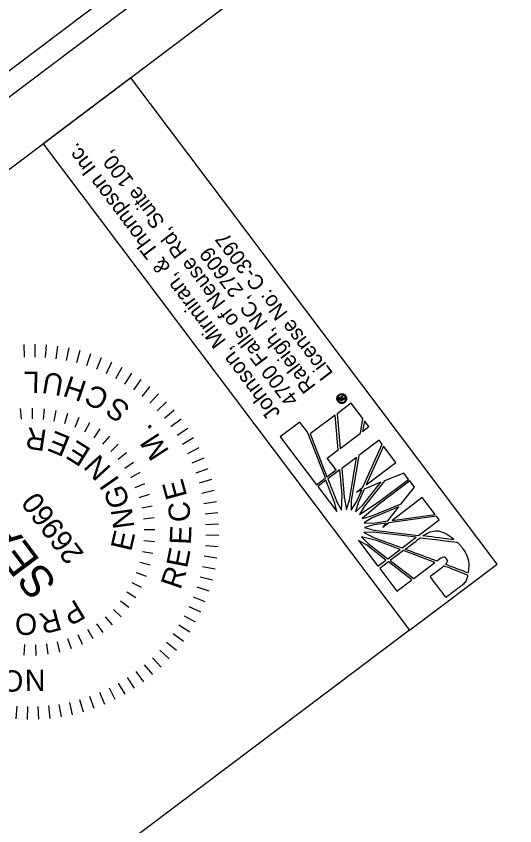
# Model space of a CAD drawing. Extents: x 1262917 to 1264804, y 775326 to 777329.
# Drawn here: x 1263048.7 to 1263156.4, y 776605.9 to 776780.7 of the extents above; entities that cross this region are included whole.
import ezdxf

# ---------------------------------------------------------------- set-up
doc = ezdxf.new("R2010")
doc.units = 0
for name, color, linetype in [('Default', 7, 'Continuous'), ('Sheet Data Field CELL', 7, 'Continuous'), ('Sheet Plan CELL', 7, 'Continuous'), ('Sheet Plot Border Inside CELL', 7, 'Continuous'), ('Sheet Plot Border Outside CELL', 7, 'Continuous'), ('Sheet Typical CELL', 7, 'Continuous')]:
    doc.layers.add(name, color=color, linetype=linetype)

msp = doc.modelspace()

# ---------------------------------------------------------------- linework, layer by layer
at = {"layer": 'Default'}
for p, q in [((1263050.34, 776709.83), (1263050.45, 776707.08)), ((1263052.78, 776709.86), (1263052.73, 776707.1)), ((1263055.23, 776709.74), (1263055, 776706.99)), ((1263057.65, 776709.47), (1263057.27, 776706.73)), ((1263060.06, 776709.05), (1263059.51, 776706.35)), ((1263062.45, 776708.49), (1263061.73, 776705.83)), ((1263064.79, 776707.79), (1263063.92, 776705.17)), ((1263067.08, 776706.94), (1263066.06, 776704.38)), ((1263069.33, 776705.96), (1263068.14, 776703.47)), ((1263071.5, 776704.84), (1263070.17, 776702.43)), ((1263073.61, 776703.6), (1263072.13, 776701.27)), ((1263075.63, 776702.24), (1263074.02, 776700)), ((1263077.58, 776700.75), (1263075.83, 776698.61)), ((1263079.42, 776699.14), (1263077.55, 776697.12)), ((1263081.17, 776697.43), (1263079.18, 776695.52)), ((1263049.6, 776695.96), (1263049.81, 776693.67)), ((1263052.19, 776696.07), (1263052.17, 776693.76)), ((1263054.76, 776695.92), (1263054.52, 776693.63)), ((1263057.3, 776695.53), (1263056.85, 776693.27)), ((1263082.81, 776695.62), (1263080.71, 776693.83)), ((1263059.8, 776694.89), (1263059.13, 776692.69)), ((1263062.23, 776694.02), (1263061.35, 776691.89)), ((1263084.34, 776693.71), (1263082.13, 776692.05)), ((1263064.56, 776692.91), (1263063.47, 776690.88)), ((1263066.78, 776691.58), (1263065.5, 776689.67)), ((1263085.75, 776691.71), (1263083.45, 776690.19)), ((1263068.85, 776690.05), (1263067.39, 776688.27)), ((1263070.76, 776688.33), (1263069.14, 776686.7)), ((1263087.03, 776689.63), (1263084.65, 776688.25)), ((1263072.51, 776686.43), (1263070.73, 776684.96)), ((1263088.19, 776687.48), (1263085.73, 776686.24)), ((1263089.22, 776685.26), (1263086.68, 776684.17)), ((1263074.06, 776684.37), (1263072.15, 776683.07)), ((1263090.11, 776682.98), (1263087.51, 776682.05)), ((1263075.4, 776682.16), (1263073.38, 776681.06)), ((1263074.41, 776678.93), (1263076.53, 776679.83)), ((1263090.86, 776680.65), (1263088.21, 776679.88)), ((1263091.47, 776678.28), (1263088.78, 776677.67)), ((1263077.42, 776677.43), (1263075.22, 776676.73)), ((1263091.94, 776675.88), (1263089.21, 776675.44)), ((1263078.07, 776674.93), (1263075.82, 776674.45)), ((1263078.49, 776672.39), (1263076.2, 776672.13)), ((1263092.26, 776673.46), (1263089.51, 776673.18)), ((1263092.43, 776671.02), (1263089.67, 776670.91)), ((1263078.65, 776669.81), (1263076.36, 776669.78)), ((1263078.57, 776667.23), (1263076.28, 776667.42)), ((1263092.45, 776668.57), (1263089.7, 776668.63)), ((1263092.33, 776666.13), (1263089.58, 776666.35)), ((1263078.24, 776664.68), (1263075.98, 776665.09)), ((1263092.06, 776663.7), (1263089.33, 776664.09)), ((1263077.67, 776662.17), (1263075.45, 776662.79)), ((1263091.65, 776661.29), (1263088.94, 776661.84)), ((1263076.85, 776659.72), (1263074.71, 776660.55)), ((1263075.8, 776657.37), (1263073.75, 776658.4)), ((1263091.08, 776658.91), (1263088.42, 776659.62)), ((1263090.38, 776656.57), (1263087.77, 776657.44)), ((1263074.53, 776655.12), (1263072.59, 776656.35)), ((1263089.54, 776654.27), (1263086.98, 776655.3)), ((1263073.05, 776653.01), (1263071.24, 776654.42)), ((1263088.56, 776652.03), (1263086.06, 776653.21)), ((1263071.37, 776651.06), (1263069.7, 776652.63)), ((1263069.51, 776649.27), (1263068, 776651)), ((1263087.44, 776649.85), (1263085.03, 776651.18)), ((1263065.32, 776646.27), (1263064.17, 776648.26)), ((1263067.49, 776647.67), (1263066.16, 776649.54)), ((1263086.2, 776647.74), (1263083.86, 776649.22)), ((1263060.63, 776644.14), (1263059.88, 776646.31)), ((1263063.03, 776645.09), (1263062.08, 776647.18)), ((1263084.83, 776645.72), (1263082.59, 776647.34)), ((1263050.48, 776642.74), (1263050.6, 776645.03)), ((1263053.05, 776642.71), (1263052.96, 776645.01)), ((1263055.62, 776642.94), (1263055.31, 776645.22)), ((1263058.16, 776643.42), (1263057.62, 776645.66)), ((1263083.34, 776643.78), (1263081.21, 776645.52)), ((1263081.74, 776641.93), (1263079.71, 776643.8)), ((1263080.03, 776640.19), (1263078.12, 776642.17)), ((1263076.3, 776637.02), (1263074.65, 776639.22)), ((1263078.21, 776638.55), (1263076.43, 776640.65)), ((1263074.3, 776635.61), (1263072.78, 776637.91)), ((1263070.07, 776633.16), (1263068.84, 776635.63)), ((1263072.22, 776634.32), (1263070.84, 776636.71)), ((1263065.57, 776631.24), (1263064.64, 776633.84)), ((1263067.85, 776632.13), (1263066.77, 776634.67)), ((1263058.48, 776629.42), (1263058.03, 776632.14)), ((1263060.88, 776629.89), (1263060.27, 776632.57)), ((1263063.25, 776630.49), (1263062.48, 776633.14)), ((1263048.72, 776629.02), (1263048.95, 776631.77)), ((1263051.17, 776628.9), (1263051.22, 776631.66)), ((1263053.61, 776628.92), (1263053.5, 776631.68)), ((1263056.05, 776629.1), (1263055.78, 776631.84))]:
    msp.add_line(p, q, dxfattribs=at)
at = {"layer": 'Sheet Data Field CELL'}
for p, q in [((1263119.67, 776698.63), (1263119.84, 776698.76)), ((1263119.84, 776698.76), (1263119.67, 776698.63)), ((1263119.67, 776698.63), (1263119.67, 776698.64)), ((1263119.83, 776698.76), (1263119.84, 776698.76)), ((1263121.05, 776697.16), (1263118.01, 776694.86)), ((1263118.19, 776697.51), (1263118.34, 776697.63)), ((1263118.34, 776697.63), (1263118.19, 776697.51)), ((1263118.63, 776697.84), (1263118.59, 776697.89)), ((1263118.63, 776697.84), (1263118.77, 776697.95)), ((1263118.77, 776697.95), (1263118.63, 776697.84)), ((1263118.86, 776697.54), (1263118.63, 776697.84)), ((1263118.76, 776697.97), (1263118.77, 776697.95)), ((1263118.77, 776697.95), (1263118.88, 776697.82)), ((1263119.61, 776698.1), (1263118.86, 776697.54)), ((1263118.88, 776697.82), (1263119.05, 776697.95)), ((1263118.95, 776698.09), (1263119.09, 776698.19)), ((1263119.09, 776698.19), (1263118.95, 776698.09)), ((1263119.05, 776697.95), (1263118.95, 776698.09)), ((1263118.95, 776698.09), (1263118.95, 776698.09)), ((1263119.08, 776698.2), (1263119.09, 776698.19)), ((1263119.09, 776698.19), (1263119.19, 776698.05)), ((1263119.19, 776698.05), (1263119.48, 776698.27)), ((1263119.48, 776698.27), (1263119.61, 776698.1)), ((1263123.56, 776693.83), (1263121.05, 776697.16)), ((1263117.62, 776694.58), (1263112.21, 776690.49)), ((1263118.24, 776687.06), (1263117.62, 776694.58)), ((1263118.01, 776694.86), (1263118.64, 776687.36)), ((1263123.03, 776690.68), (1263123.56, 776693.83)), ((1263123.93, 776693.35), (1263123.51, 776691.04)), ((1263124.89, 776692.08), (1263123.93, 776693.35)), ((1263109.97, 776693.06), (1263105.75, 776689.87)), ((1263111.63, 776690.86), (1263109.97, 776693.06)), ((1263123.51, 776691.04), (1263124.89, 776692.08)), ((1263105.75, 776689.87), (1263113.53, 776679.55)), ((1263115.48, 776681.02), (1263111.63, 776690.86)), ((1263112.21, 776690.49), (1263115.78, 776681.24)), ((1263118.64, 776687.36), (1263123.03, 776690.68)), ((1263127.1, 776689.14), (1263122.7, 776685.82)), ((1263123.6, 776678.99), (1263127.76, 776688.28)), ((1263127.76, 776688.28), (1263127.1, 776689.14)), ((1263115.88, 776685.28), (1263118.24, 776687.06)), ((1263128.04, 776687.85), (1263124.31, 776679.52)), ((1263130.69, 776684.34), (1263128.04, 776687.85)), ((1263117.78, 776682.76), (1263115.88, 776685.28)), ((1263122.19, 776685.43), (1263119.04, 776683.06)), ((1263120.67, 776676.18), (1263122.19, 776685.43)), ((1263122.7, 776685.82), (1263121.07, 776676.14)), ((1263115.81, 776681.27), (1263117.78, 776682.76)), ((1263119.04, 776683.06), (1263119.55, 776676.82)), ((1263124.31, 776679.52), (1263130.69, 776684.34)), ((1263115.43, 776680.98), (1263115.48, 776681.02)), ((1263115.78, 776681.24), (1263115.81, 776681.27)), ((1263118.61, 776682.73), (1263115.98, 776680.8)), ((1263119.08, 776677.39), (1263118.61, 776682.73)), ((1263132.41, 776682.06), (1263128.23, 776680.4)), ((1263133.43, 776680.7), (1263132.41, 776682.06)), ((1263113.53, 776679.55), (1263115.43, 776680.98)), ((1263115.61, 776680.52), (1263113.84, 776679.19)), ((1263117.54, 776675.59), (1263115.61, 776680.52)), ((1263115.98, 776680.8), (1263118, 776675.73)), ((1263123.47, 776675.06), (1263127.46, 776680.07)), ((1263127.46, 776680.07), (1263123.89, 776678.61)), ((1263128.23, 776680.4), (1263123.91, 776674.93)), ((1263126.89, 776675.76), (1263133.43, 776680.7)), ((1263133.7, 776680.36), (1263127.15, 776675.42)), ((1263134.71, 776679.01), (1263133.7, 776680.36)), ((1263113.84, 776679.19), (1263117.93, 776673.73)), ((1263122.17, 776677.91), (1263123.6, 776678.99)), ((1263122.17, 776675.87), (1263123.33, 776678.39)), ((1263123.33, 776678.39), (1263122.17, 776677.91)), ((1263123.89, 776678.61), (1263122.55, 776675.6)), ((1263131.87, 776675.42), (1263134.71, 776679.01)), ((1263118.94, 776674.07), (1263119.08, 776677.39)), ((1263119.55, 776676.82), (1263120.03, 776674.21)), ((1263120.03, 776674.21), (1263120.67, 776676.18)), ((1263121.07, 776676.14), (1263121.05, 776674.08)), ((1263121.05, 776674.08), (1263122.17, 776675.87)), ((1263122.83, 776673.09), (1263126.89, 776675.76)), ((1263136.41, 776676.81), (1263129.89, 776671.84)), ((1263139.17, 776673.15), (1263136.41, 776676.81)), ((1263117.93, 776673.73), (1263117.54, 776675.59)), ((1263118, 776675.73), (1263118.94, 776674.07)), ((1263122.55, 776675.6), (1263122.02, 776673.71)), ((1263122.02, 776673.71), (1263123.47, 776675.06)), ((1263123.91, 776674.93), (1263122.83, 776673.09)), ((1263127.15, 776675.42), (1263123.44, 776672.28)), ((1263131.31, 776674.74), (1263125.45, 776672.31)), ((1263125.52, 776672.8), (1263131.87, 776675.42)), ((1263128.96, 776671.73), (1263131.31, 776674.74)), ((1263123.44, 776672.28), (1263125.52, 776672.8)), ((1263125.45, 776672.31), (1263123.83, 776671.31)), ((1263139.46, 776672.77), (1263129.19, 776671.31)), ((1263129.89, 776671.84), (1263139.17, 776673.15)), ((1263140.07, 776671.96), (1263139.46, 776672.77)), ((1263123.83, 776671.31), (1263125.81, 776671.28)), ((1263125.95, 776670.86), (1263123.93, 776670.28)), ((1263125.81, 776671.28), (1263128.96, 776671.73)), ((1263128.6, 776671.24), (1263125.95, 776670.86)), ((1263129.19, 776671.31), (1263127.89, 776670.33)), ((1263127.89, 776670.33), (1263128.6, 776671.24)), ((1263135.62, 776668.6), (1263140.07, 776671.96)), ((1263125.81, 776669.32), (1263123.76, 776669.26)), ((1263123.76, 776669.26), (1263126.12, 776668.11)), ((1263123.93, 776670.28), (1263125.92, 776669.73)), ((1263135.1, 776668.21), (1263125.81, 776669.32)), ((1263125.92, 776669.73), (1263135.62, 776668.6)), ((1263124.33, 776666.54), (1263122.65, 776667.48)), ((1263122.65, 776667.48), (1263126.81, 776661.95)), ((1263126.49, 776667.5), (1263123.31, 776668.28)), ((1263123.31, 776668.28), (1263124.71, 776666.83)), ((1263126.12, 776668.11), (1263132.04, 776665.9)), ((1263131.61, 776665.57), (1263126.49, 776667.5)), ((1263132.04, 776665.9), (1263135.1, 776668.21)), ((1263128.57, 776663.28), (1263124.33, 776666.54)), ((1263124.71, 776666.83), (1263128.95, 776663.57)), ((1263128.95, 776663.57), (1263131.61, 776665.57)), ((1263132.32, 776665.31), (1263129.47, 776663.16)), ((1263139.13, 776662.75), (1263132.32, 776665.31)), ((1263126.81, 776661.95), (1263128.57, 776663.28)), ((1263129.12, 776662.89), (1263127.22, 776661.46)), ((1263134.18, 776659.01), (1263129.12, 776662.89)), ((1263129.47, 776663.16), (1263134.55, 776659.29)), ((1263134.55, 776659.29), (1263139.13, 776662.75)), ((1263127.22, 776661.46), (1263130.93, 776656.55)), ((1263130.93, 776656.55), (1263134.18, 776659.01))]:
    msp.add_line(p, q, dxfattribs=at)
msp.add_lwpolyline([(1263152.54, 776662.43), (1263073.5, 776767.37), (1263054.56, 776753.11), (1263133.61, 776648.16)], close=True, dxfattribs=at)
for points in [[(1263118.96, 776698.6), (1263119, 776698.64), (1263119.02, 776698.66), (1263119.05, 776698.68), (1263119.11, 776698.77), (1263119.23, 776698.61)], [(1263118.64, 776687.36), (1263123.03, 776690.68), (1263123.56, 776693.83), (1263121.05, 776697.16), (1263118.01, 776694.86), (1263118.64, 776687.36), (1263118.64, 776687.36)], [(1263115.78, 776681.24), (1263115.81, 776681.27), (1263117.78, 776682.76), (1263115.88, 776685.28), (1263118.24, 776687.06), (1263117.62, 776694.58), (1263112.21, 776690.49), (1263115.78, 776681.24)], [(1263124.89, 776692.08), (1263124.89, 776692.08), (1263123.93, 776693.35), (1263123.51, 776691.04), (1263124.89, 776692.08)], [(1263105.75, 776689.87), (1263113.53, 776679.55), (1263115.43, 776680.98), (1263115.48, 776681.02), (1263111.63, 776690.86), (1263109.97, 776693.06), (1263105.75, 776689.87)], [(1263121.05, 776674.08), (1263122.17, 776675.87), (1263123.33, 776678.39), (1263122.17, 776677.91), (1263123.6, 776678.99), (1263127.76, 776688.28), (1263127.1, 776689.14), (1263122.7, 776685.82), (1263121.07, 776676.14), (1263121.05, 776674.08)], [(1263130.69, 776684.34), (1263128.04, 776687.85), (1263124.31, 776679.52), (1263130.69, 776684.34)], [(1263120.03, 776674.21), (1263120.67, 776676.18), (1263122.19, 776685.43), (1263119.04, 776683.06), (1263119.55, 776676.82), (1263120.03, 776674.21)], [(1263118.94, 776674.07), (1263119.08, 776677.39), (1263118.61, 776682.73), (1263115.98, 776680.8), (1263118, 776675.73), (1263118.94, 776674.07)], [(1263122.83, 776673.09), (1263126.89, 776675.76), (1263133.43, 776680.7), (1263132.41, 776682.06), (1263128.23, 776680.4), (1263123.91, 776674.93), (1263122.83, 776673.09)], [(1263117.54, 776675.59), (1263115.61, 776680.52), (1263113.84, 776679.19), (1263117.93, 776673.73), (1263117.54, 776675.59)], [(1263122.02, 776673.71), (1263123.47, 776675.06), (1263127.46, 776680.07), (1263123.89, 776678.61), (1263122.55, 776675.6), (1263122.02, 776673.71)], [(1263125.52, 776672.8), (1263131.87, 776675.42), (1263134.71, 776679.01), (1263133.7, 776680.36), (1263127.15, 776675.42), (1263123.44, 776672.28), (1263125.52, 776672.8)], [(1263139.17, 776673.15), (1263136.41, 776676.81), (1263129.89, 776671.84), (1263139.17, 776673.15)], [(1263123.83, 776671.31), (1263125.81, 776671.28), (1263128.96, 776671.73), (1263131.31, 776674.74), (1263125.45, 776672.31), (1263123.83, 776671.31)], [(1263123.93, 776670.28), (1263125.92, 776669.73), (1263135.62, 776668.6), (1263140.07, 776671.96), (1263139.46, 776672.77), (1263129.19, 776671.31), (1263127.89, 776670.33), (1263128.6, 776671.24), (1263125.95, 776670.86), (1263123.93, 776670.28)], [(1263132.04, 776665.9), (1263135.1, 776668.21), (1263125.81, 776669.32), (1263123.76, 776669.26), (1263126.12, 776668.11), (1263132.04, 776665.9)], [(1263124.33, 776666.54), (1263122.65, 776667.48), (1263126.81, 776661.95), (1263128.57, 776663.28), (1263124.33, 776666.54)], [(1263128.95, 776663.57), (1263131.61, 776665.57), (1263126.49, 776667.5), (1263123.31, 776668.28), (1263124.71, 776666.83), (1263128.95, 776663.57)], [(1263139.13, 776662.75), (1263132.32, 776665.31), (1263129.47, 776663.16), (1263134.55, 776659.29), (1263139.13, 776662.75)], [(1263134.18, 776659.01), (1263129.12, 776662.89), (1263127.22, 776661.46), (1263130.93, 776656.55), (1263134.18, 776659.01)]]:
    msp.add_lwpolyline(points, dxfattribs=at)
for points, degree in [([(1263118.19, 776697.51), (1263118.01, 776697.74), (1263117.94, 776698), (1263117.98, 776698.28), (1263118, 776698.56), (1263118.14, 776698.79), (1263118.37, 776698.97)], 3), ([(1263119.67, 776698.64), (1263119.53, 776698.82), (1263119.35, 776698.93), (1263119.12, 776698.97), (1263118.89, 776699), (1263118.68, 776698.94), (1263118.5, 776698.8), (1263118.31, 776698.66), (1263118.2, 776698.47), (1263118.17, 776698.25), (1263118.14, 776698.02), (1263118.2, 776697.82), (1263118.34, 776697.63)], 3), ([(1263119.84, 776698.76), (1263120.01, 776698.53), (1263120.07, 776698.27), (1263120.03, 776697.98), (1263120, 776697.7), (1263119.86, 776697.47), (1263119.63, 776697.3), (1263119.4, 776697.12), (1263119.14, 776697.05), (1263118.87, 776697.1), (1263118.59, 776697.15), (1263118.36, 776697.28), (1263118.19, 776697.51)], 3), ([(1263118.34, 776697.63), (1263118.48, 776697.44), (1263118.66, 776697.33), (1263118.88, 776697.3), (1263119.11, 776697.27), (1263119.33, 776697.32), (1263119.51, 776697.46), (1263119.69, 776697.6), (1263119.81, 776697.79), (1263119.84, 776698.02), (1263119.87, 776698.25), (1263119.81, 776698.45), (1263119.67, 776698.63)], 3), ([(1263118.37, 776698.97), (1263118.6, 776699.14), (1263118.86, 776699.21), (1263119.15, 776699.18), (1263119.43, 776699.13), (1263119.66, 776698.99), (1263119.83, 776698.76)], 3), ([(1263118.83, 776698.38), (1263118.82, 776698.45), (1263118.87, 776698.53), (1263118.96, 776698.6)], 2), ([(1263119.23, 776698.61), (1263119.21, 776698.56), (1263119.17, 776698.51), (1263119.12, 776698.47), (1263119.05, 776698.42), (1263119.02, 776698.38), (1263119.01, 776698.35)], 3), ([(1263118.59, 776697.89), (1263118.45, 776698.08), (1263118.45, 776698.24), (1263118.6, 776698.35), (1263118.67, 776698.4), (1263118.75, 776698.41), (1263118.83, 776698.38)], 3), ([(1263118.95, 776698.09), (1263118.86, 776698.2), (1263118.79, 776698.23), (1263118.73, 776698.19), (1263118.67, 776698.14), (1263118.68, 776698.08), (1263118.76, 776697.97)], 3), ([(1263119.01, 776698.35), (1263119.01, 776698.32), (1263119.03, 776698.26), (1263119.08, 776698.2)], 2), ([(1263136.54, 776668.5), (1263136.54, 776668.5), (1263143.37, 776667.65), (1263143.37, 776667.65), (1263141.5, 776669.17), (1263138.85, 776670.1), (1263136.54, 776668.5)], 3), ([(1263141.65, 776663.54), (1263141.87, 776663.25), (1263141.89, 776662.87), (1263141.43, 776662.36), (1263141.43, 776662.36), (1263146.27, 776660.48), (1263146.27, 776660.48), (1263146.59, 776662.43), (1263145.96, 776664.67), (1263144.86, 776666.14), (1263144.57, 776666.52), (1263144.32, 776666.79), (1263143.93, 776667.13), (1263143.93, 776667.13), (1263136.03, 776668.11), (1263136.03, 776668.11), (1263136.03, 776668.11), (1263132.72, 776665.61), (1263132.72, 776665.61), (1263132.72, 776665.61), (1263139.54, 776663.06), (1263139.54, 776663.06), (1263140.78, 776663.99), (1263141.34, 776663.94), (1263141.65, 776663.54)], 3), ([(1263141.65, 776663.54), (1263141.87, 776663.25), (1263141.89, 776662.87), (1263141.43, 776662.36), (1263141.43, 776662.36), (1263146.27, 776660.48), (1263146.27, 776660.48), (1263146.59, 776662.43), (1263145.96, 776664.67), (1263144.86, 776666.14), (1263144.57, 776666.52), (1263144.32, 776666.79), (1263143.93, 776667.13), (1263143.93, 776667.13), (1263136.03, 776668.11), (1263136.03, 776668.11), (1263136.03, 776668.11), (1263132.72, 776665.61), (1263132.72, 776665.61), (1263132.72, 776665.61), (1263139.54, 776663.06), (1263139.54, 776663.06), (1263140.78, 776663.99), (1263141.34, 776663.94), (1263141.65, 776663.54)], 3), ([(1263138.09, 776659.75), (1263138.09, 776659.75), (1263141.52, 776655.2), (1263141.52, 776655.2), (1263141.52, 776655.2), (1263144.36, 776657.35), (1263144.36, 776657.35), (1263144.36, 776657.35), (1263144.66, 776657.58), (1263144.66, 776657.58), (1263145.55, 776658.25), (1263146.03, 776659.07), (1263146.23, 776660.04), (1263146.23, 776660.04), (1263141.15, 776662.06), (1263141.09, 776662.01), (1263141.09, 776662.01), (1263138.09, 776659.75), (1263138.09, 776659.75)], 3)]:
    msp.add_open_spline(points, degree=degree, dxfattribs=at)
at = {"layer": 'Sheet Plan CELL'}
msp.add_lwpolyline([(1263054.56, 776753.11), (1263133.61, 776648.16), (1263043.77, 776580.5), (1262964.72, 776685.44)], dxfattribs=at)
at = {"layer": 'Sheet Plot Border Inside CELL'}
msp.add_lwpolyline([(1264780.22, 775982.89), (1263777.88, 777313.61), (1262935.19, 776678.9), (1263937.52, 775348.16)], close=True, dxfattribs=at)
at = {"layer": 'Sheet Plot Border Outside CELL'}
msp.add_lwpolyline([(1262916.5, 776670.46), (1263929.36, 775325.74), (1264804.01, 775984.53), (1263791.15, 777329.26)], close=True, dxfattribs=at)
at = {"layer": 'Sheet Typical CELL'}
msp.add_line((1262944.69, 776670.41), (1263783.4, 777302.14), dxfattribs=at)

# ---------------------------------------------------------------- texts
at = {"layer": 'Default'}
for s, height, rotation, p in [('L', 4.6, 179.1415, (1263053.79, 776703.9)), ('U', 4.6, 170.2588, (1263059.25, 776703.18)), ('H', 4.6, 161.3762, (1263064.24, 776701.7)), ('C', 4.6, 152.5536, (1263069.15, 776699.38)), ('S', 4.6, 143.551, (1263073.63, 776696.33)), ('R', 4.6, 171.4993, (1263055.53, 776691.31)), ('.', 4.6, 130.7667, (1263078.38, 776691.66)), ('E', 4.6, 157.7282, (1263060.72, 776689.73)), ('M', 4.6, 123.0244, (1263081.87, 776686.78)), ('E', 4.6, 147.7423, (1263065.12, 776687.14)), ('N', 4.6, 132.3503, (1263069.44, 776683.11)), ('I', 4.6, 124.7206, (1263071.19, 776680.52)), ('E', 4.6, 105.229, (1263085.67, 776677.1)), ('26960', 4.596, 126.9344, (1263063.5, 776664.67)), ('G', 4.6, 106.6258, (1263073.3, 776675.26)), ('SEAL', 6.899, 126.9344, (1263057.75, 776658.25)), ('C', 4.6, 96.2566, (1263086.47, 776671.74)), ('N', 4.6, 97.8596, (1263074.28, 776670.37)), ('E', 4.6, 77.0045, (1263073.54, 776664.98)), ('E', 4.6, 87.584, (1263086.43, 776666.53)), ('E', 4.6, 78.9412, (1263085.61, 776661.38)), ('R', 4.6, 70.8694, (1263084.15, 776656.72)), ('P', 4.6, 211.0638, (1263061.68, 776654.96)), ('O', 4.6, 180.4713, (1263053.23, 776651.75)), ('R', 4.6, 195.7675, (1263057.62, 776652.78)), ('O', 4.6, 178.6517, (1263050.31, 776639.43)), ('N', 4.6, 180.6111, (1263055, 776639.65))]:
    msp.add_text(s, height=height, rotation=rotation, dxfattribs=at).set_placement(p)
at = {"layer": 'Sheet Data Field CELL'}
for s, height, p in [('Johnson, Mirmiran, & Thompson Inc.', 3.357, (1263105.9, 776695.03)), ('4700 Falls of Neuse Rd, Suite 100, ', 3.2611, (1263109.84, 776698)), ('License No: C-3097', 3.2611, (1263117.28, 776703.6)), ('Raleigh, NC, 27609', 3.2611, (1263113.56, 776700.8))]:
    msp.add_text(s, height=height, rotation=126.9874, dxfattribs=at).set_placement(p)

doc.saveas('drawing.dxf')
